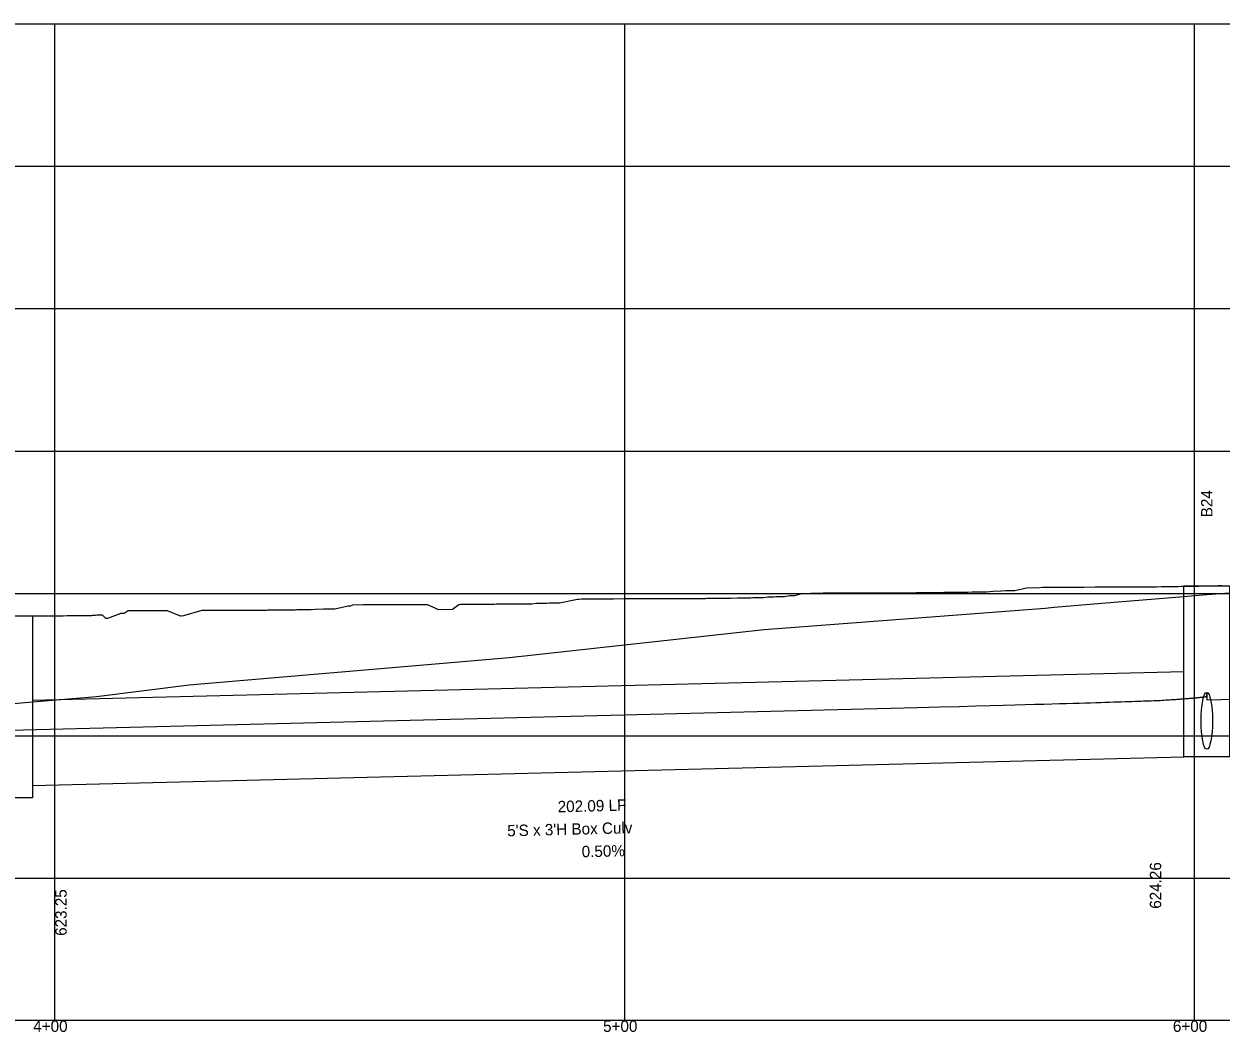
# Model space of a CAD drawing. Extents: x 2253035 to 2279930, y 13774972 to 13793443.
# Drawn here: x 2260421 to 2260631.1, y 13791296.5 to 13791473.6 of the extents above; entities that cross this region are included whole.
import ezdxf

# ---------------------------------------------------------------- set-up
doc = ezdxf.new("R2010")
doc.units = 0
for name, color, linetype in [('Default', 7, 'Continuous'), ('E_Utility_ATT_HH', 7, 'Continuous'), ('E_Utility_ATT_PR_PVC', 7, 'Continuous'), ('E_Utillity_Water_Water Line_12in', 7, 'Continuous'), ('E_Utillity_Water_Water Line_1in', 7, 'Continuous'), ('E_Utillity_Water_Water Line_4in', 7, 'Continuous'), ('E_Utillity_Water_Water Line_8in', 7, 'Continuous')]:
    doc.layers.add(name, color=color, linetype=linetype)

msp = doc.modelspace()

# ---------------------------------------------------------------- linework, layer by layer
at = {"layer": 'Default'}
for p, q in [((2260426.46, 13791298.56), (2260426.46, 13791473.56)), ((2260526.46, 13791298.56), (2260526.46, 13791473.56)), ((2260626.46, 13791298.56), (2260626.46, 13791473.56)), ((2260026.46, 13791448.56), (2261320.64, 13791448.56)), ((2260026.46, 13791423.56), (2261320.64, 13791423.56)), ((2260026.46, 13791398.56), (2261320.64, 13791398.56)), ((2260026.46, 13791373.56), (2261320.64, 13791373.56)), ((2260026.46, 13791348.56), (2261320.64, 13791348.56)), ((2260026.46, 13791323.56), (2261320.64, 13791323.56))]:
    msp.add_line(p, q, dxfattribs=at)
msp.add_lwpolyline([(2260026.46, 13791298.56), (2260026.46, 13791473.56), (2261320.64, 13791473.56), (2261320.64, 13791298.56)], close=True, dxfattribs=at)
at = {"layer": 'E_Utility_ATT_PR_PVC'}
msp.add_line((2260628.6, 13791355.98), (2260628.6, 13791354.84), dxfattribs=at)
for points in [[(2260418.51, 13791349.55), (2260577.85, 13791353.53), (2260581.79, 13791353.63), (2260585.13, 13791353.72), (2260588.03, 13791353.8), (2260590.57, 13791353.87), (2260592.84, 13791353.93), (2260594.89, 13791353.99), (2260596.74, 13791354.04), (2260598.43, 13791354.08), (2260599.99, 13791354.13), (2260601.42, 13791354.17), (2260602.75, 13791354.21), (2260603.99, 13791354.24), (2260605.15, 13791354.28), (2260606.24, 13791354.31), (2260607.26, 13791354.34), (2260608.22, 13791354.37), (2260609.12, 13791354.4), (2260609.98, 13791354.42), (2260610.79, 13791354.45), (2260611.56, 13791354.47), (2260612.29, 13791354.5), (2260612.98, 13791354.52), (2260613.65, 13791354.54), (2260614.28, 13791354.56), (2260614.88, 13791354.58), (2260615.45, 13791354.6), (2260616.01, 13791354.62), (2260616.53, 13791354.64), (2260617.04, 13791354.65), (2260617.52, 13791354.67), (2260617.98, 13791354.69), (2260618.43, 13791354.7), (2260618.85, 13791354.72), (2260619.26, 13791354.74), (2260619.66, 13791354.75), (2260620.04, 13791354.76), (2260620.4, 13791354.78), (2260620.75, 13791354.8), (2260621.09, 13791354.82), (2260621.41, 13791354.84), (2260621.73, 13791354.86), (2260622.03, 13791354.88), (2260622.32, 13791354.9), (2260622.6, 13791354.92), (2260622.87, 13791354.94), (2260623.12, 13791354.95), (2260623.37, 13791354.97), (2260623.62, 13791354.99), (2260623.85, 13791355.01), (2260624.07, 13791355.02), (2260624.29, 13791355.04), (2260624.49, 13791355.05), (2260624.69, 13791355.07), (2260624.89, 13791355.08), (2260625.07, 13791355.1), (2260625.25, 13791355.11), (2260625.42, 13791355.12), (2260625.59, 13791355.14), (2260625.75, 13791355.15), (2260625.9, 13791355.16), (2260626.05, 13791355.18), (2260626.19, 13791355.19), (2260626.33, 13791355.2), (2260626.46, 13791355.21), (2260626.59, 13791355.22), (2260626.71, 13791355.23), (2260626.83, 13791355.24), (2260626.94, 13791355.26), (2260627.05, 13791355.27), (2260627.15, 13791355.28), (2260627.25, 13791355.29), (2260627.34, 13791355.3), (2260627.43, 13791355.31), (2260627.52, 13791355.31), (2260627.6, 13791355.32), (2260627.68, 13791355.33), (2260627.75, 13791355.34), (2260627.82, 13791355.35), (2260627.89, 13791355.36), (2260627.95, 13791355.37), (2260628.01, 13791355.37), (2260628.07, 13791355.38), (2260628.12, 13791355.39), (2260628.17, 13791355.4), (2260628.22, 13791355.4), (2260628.26, 13791355.41), (2260628.3, 13791355.42), (2260628.34, 13791355.43), (2260628.38, 13791355.43), (2260628.41, 13791355.44), (2260628.44, 13791355.45), (2260628.47, 13791355.45), (2260628.49, 13791355.46), (2260628.51, 13791355.46), (2260628.53, 13791355.47), (2260628.55, 13791355.48), (2260628.56, 13791355.48), (2260628.58, 13791355.49), (2260628.59, 13791355.49), (2260628.59, 13791355.5), (2260628.6, 13791355.5), (2260628.6, 13791355.51), (2260628.6, 13791355.51), (2260628.6, 13791355.98)], [(2260628.6, 13791354.84), (2260648.65, 13791355.34)]]:
    msp.add_lwpolyline(points, dxfattribs=at)
at = {"layer": 'E_Utillity_Water_Water Line_12in'}
for points in [[(2260624.6, 13791374.89), (2260632.6, 13791374.89), (2260632.6, 13791344.86), (2260624.6, 13791344.86)], [(2260414.51, 13791369.59), (2260422.51, 13791369.59), (2260422.51, 13791337.66), (2260414.51, 13791337.66)]]:
    msp.add_lwpolyline(points, close=True, dxfattribs=at)
at = {"layer": 'E_Utillity_Water_Water Line_1in'}
msp.add_lwpolyline([(2260418.51, 13791354.19), (2260422.51, 13791354.51), (2260422.51, 13791354.51), (2260433.72, 13791355.44), (2260450.02, 13791357.49), (2260494.56, 13791361.29), (2260506.17, 13791362.32), (2260550.9, 13791367.22), (2260600.22, 13791370.98), (2260601.83, 13791371.13), (2260610.17, 13791371.83), (2260624.6, 13791373.04), (2260624.6, 13791373.04), (2260628.6, 13791373.36), (2260628.6, 13791373.36), (2260632.6, 13791373.68)], dxfattribs=at)
at = {"layer": 'E_Utillity_Water_Water Line_4in'}
for p, q in [((2260422.51, 13791354.8), (2260624.6, 13791359.86)), ((2260422.51, 13791339.8), (2260624.6, 13791344.86))]:
    msp.add_line(p, q, dxfattribs=at)
msp.add_ellipse((2260628.6, 13791351.18), major_axis=(0, 5), ratio=0.2, dxfattribs=at)
at = {"layer": 'E_Utillity_Water_Water Line_8in'}
msp.add_lwpolyline([(2260420, 13791369.6), (2260422.51, 13791369.61), (2260422.51, 13791369.61), (2260422.58, 13791369.61), (2260423.6, 13791369.61), (2260425.07, 13791369.61), (2260425.24, 13791369.62), (2260427.59, 13791369.63), (2260427.77, 13791369.64), (2260427.92, 13791369.64), (2260428.6, 13791369.65), (2260430.31, 13791369.65), (2260430.69, 13791369.69), (2260432.86, 13791369.7), (2260433.11, 13791369.73), (2260433.26, 13791369.73), (2260433.6, 13791369.74), (2260433.82, 13791369.77), (2260434.77, 13791369.78), (2260435.31, 13791369.23), (2260435.72, 13791369.23), (2260438.05, 13791370.09), (2260438.23, 13791370.09), (2260438.6, 13791370.1), (2260438.63, 13791370.1), (2260439.33, 13791370.56), (2260439.82, 13791370.56), (2260439.83, 13791370.56), (2260443.33, 13791370.56), (2260443.38, 13791370.56), (2260443.6, 13791370.56), (2260443.84, 13791370.56), (2260443.85, 13791370.56), (2260446.12, 13791370.56), (2260448.42, 13791369.59), (2260448.52, 13791369.59), (2260448.6, 13791369.59), (2260449.08, 13791369.7), (2260452.28, 13791370.6), (2260453.67, 13791370.6), (2260455.18, 13791370.6), (2260455.33, 13791370.61), (2260455.45, 13791370.61), (2260457.54, 13791370.61), (2260457.57, 13791370.61), (2260458.6, 13791370.62), (2260458.65, 13791370.62), (2260459.85, 13791370.62), (2260462.03, 13791370.62), (2260462.33, 13791370.64), (2260463.6, 13791370.64), (2260463.81, 13791370.66), (2260465.22, 13791370.66), (2260467.45, 13791370.67), (2260467.79, 13791370.69), (2260467.96, 13791370.69), (2260468.6, 13791370.7), (2260468.92, 13791370.72), (2260469.6, 13791370.73), (2260471.43, 13791370.73), (2260472.14, 13791370.81), (2260473.6, 13791370.82), (2260473.87, 13791370.82), (2260475.58, 13791370.83), (2260477.92, 13791371.37), (2260478.04, 13791371.37), (2260478.1, 13791371.37), (2260478.32, 13791371.38), (2260478.34, 13791371.38), (2260478.6, 13791371.49), (2260478.74, 13791371.56), (2260480.53, 13791371.6), (2260484.19, 13791371.61), (2260486.28, 13791371.61), (2260486.32, 13791371.61), (2260488.5, 13791371.62), (2260488.99, 13791371.62), (2260489.54, 13791371.62), (2260491.76, 13791371.62), (2260493.76, 13791370.76), (2260496.24, 13791370.77), (2260497.36, 13791371.63), (2260497.62, 13791371.64), (2260498.6, 13791371.64), (2260498.97, 13791371.66), (2260500.24, 13791371.66), (2260502.21, 13791371.67), (2260502.38, 13791371.68), (2260503.6, 13791371.68), (2260503.9, 13791371.7), (2260504.83, 13791371.7), (2260506.75, 13791371.71), (2260507.24, 13791371.74), (2260508.6, 13791371.75), (2260510.12, 13791371.75), (2260510.91, 13791371.83), (2260512.72, 13791371.84), (2260513.21, 13791371.91), (2260513.33, 13791371.91), (2260513.6, 13791371.91), (2260515.02, 13791371.92), (2260518.14, 13791372.56), (2260518.39, 13791372.56), (2260518.93, 13791372.58), (2260520.91, 13791372.63), (2260524.27, 13791372.63), (2260524.48, 13791372.63), (2260526.47, 13791372.64), (2260526.51, 13791372.64), (2260526.55, 13791372.64), (2260528.68, 13791372.64), (2260529.15, 13791372.64), (2260531.05, 13791372.64), (2260533.01, 13791372.65), (2260533.74, 13791372.65), (2260535.18, 13791372.65), (2260537.28, 13791372.65), (2260537.63, 13791372.67), (2260538.6, 13791372.67), (2260538.63, 13791372.67), (2260538.84, 13791372.68), (2260540.12, 13791372.68), (2260540.54, 13791372.69), (2260540.65, 13791372.69), (2260540.84, 13791372.7), (2260542.71, 13791372.71), (2260543.44, 13791372.71), (2260543.95, 13791372.71), (2260545.12, 13791372.71), (2260546.23, 13791372.79), (2260547, 13791372.79), (2260548.55, 13791372.79), (2260548.6, 13791372.8), (2260548.95, 13791372.83), (2260549.53, 13791372.83), (2260549.81, 13791372.86), (2260550.78, 13791372.86), (2260551.55, 13791372.94), (2260552.59, 13791372.94), (2260552.95, 13791372.99), (2260553.6, 13791372.99), (2260553.84, 13791373.03), (2260554.49, 13791373.03), (2260555.44, 13791373.19), (2260555.78, 13791373.2), (2260556.32, 13791373.2), (2260557.54, 13791373.56), (2260559.1, 13791373.6), (2260559.36, 13791373.6), (2260561.29, 13791373.65), (2260564.56, 13791373.66), (2260564.76, 13791373.66), (2260567.44, 13791373.66), (2260567.48, 13791373.66), (2260568.85, 13791373.66), (2260569.31, 13791373.66), (2260569.83, 13791373.67), (2260572.3, 13791373.67), (2260573.78, 13791373.67), (2260575.18, 13791373.67), (2260577.22, 13791373.68), (2260577.66, 13791373.7), (2260578.6, 13791373.7), (2260579.21, 13791373.73), (2260580.39, 13791373.73), (2260582.21, 13791373.73), (2260582.48, 13791373.75), (2260583.6, 13791373.75), (2260584.08, 13791373.78), (2260584.92, 13791373.78), (2260586.65, 13791373.79), (2260587.41, 13791373.84), (2260588.6, 13791373.85), (2260589.93, 13791373.85), (2260591.13, 13791373.97), (2260592.59, 13791373.98), (2260593.31, 13791374.08), (2260593.4, 13791374.08), (2260593.6, 13791374.08), (2260593.77, 13791374.08), (2260594.89, 13791374.09), (2260596.95, 13791374.56), (2260599.29, 13791374.62), (2260599.8, 13791374.63), (2260601.67, 13791374.68), (2260604.85, 13791374.68), (2260605.05, 13791374.68), (2260606.93, 13791374.68), (2260606.97, 13791374.68), (2260607.01, 13791374.68), (2260609.02, 13791374.69), (2260609.47, 13791374.69), (2260611.27, 13791374.69), (2260613.13, 13791374.69), (2260613.82, 13791374.7), (2260614.6, 13791374.7), (2260616.79, 13791374.7), (2260617.32, 13791374.72), (2260617.44, 13791374.72), (2260618.6, 13791374.73), (2260618.75, 13791374.73), (2260619.77, 13791374.74), (2260620.68, 13791374.78), (2260622.78, 13791374.79), (2260623.6, 13791374.79), (2260624.17, 13791374.82), (2260624.6, 13791374.82), (2260624.6, 13791374.82), (2260625.32, 13791374.82), (2260627.14, 13791374.83), (2260627.98, 13791374.89), (2260628.11, 13791374.89), (2260628.6, 13791374.89), (2260628.6, 13791374.89), (2260628.6, 13791374.89), (2260629.85, 13791374.9), (2260631.21, 13791375.03)], dxfattribs=at)

# ---------------------------------------------------------------- texts
at = {"layer": 'Default'}
for s, p in [('4+00', (2260422.65, 13791296.56)), ('5+00', (2260522.65, 13791296.56)), ('6+00', (2260622.65, 13791296.56))]:
    msp.add_text(s, height=2, dxfattribs=at).set_placement(p)
at = {"layer": 'E_Utility_ATT_HH'}
for s, rotation, p in [('B24', 90, (2260629.6, 13791386.93)), ('202.09 LF', 1.4321, (2260514.71, 13791335.11)), ("5'S x 3'H Box Culv", 1.4321, (2260505.85, 13791330.89)), ('0.50%', 1.4321, (2260518.92, 13791327.21)), ('624.26', 90, (2260620.6, 13791318.18)), ('623.25', 90, (2260428.51, 13791313.42))]:
    msp.add_text(s, height=2, rotation=rotation, dxfattribs=at).set_placement(p)

doc.saveas('drawing.dxf')
